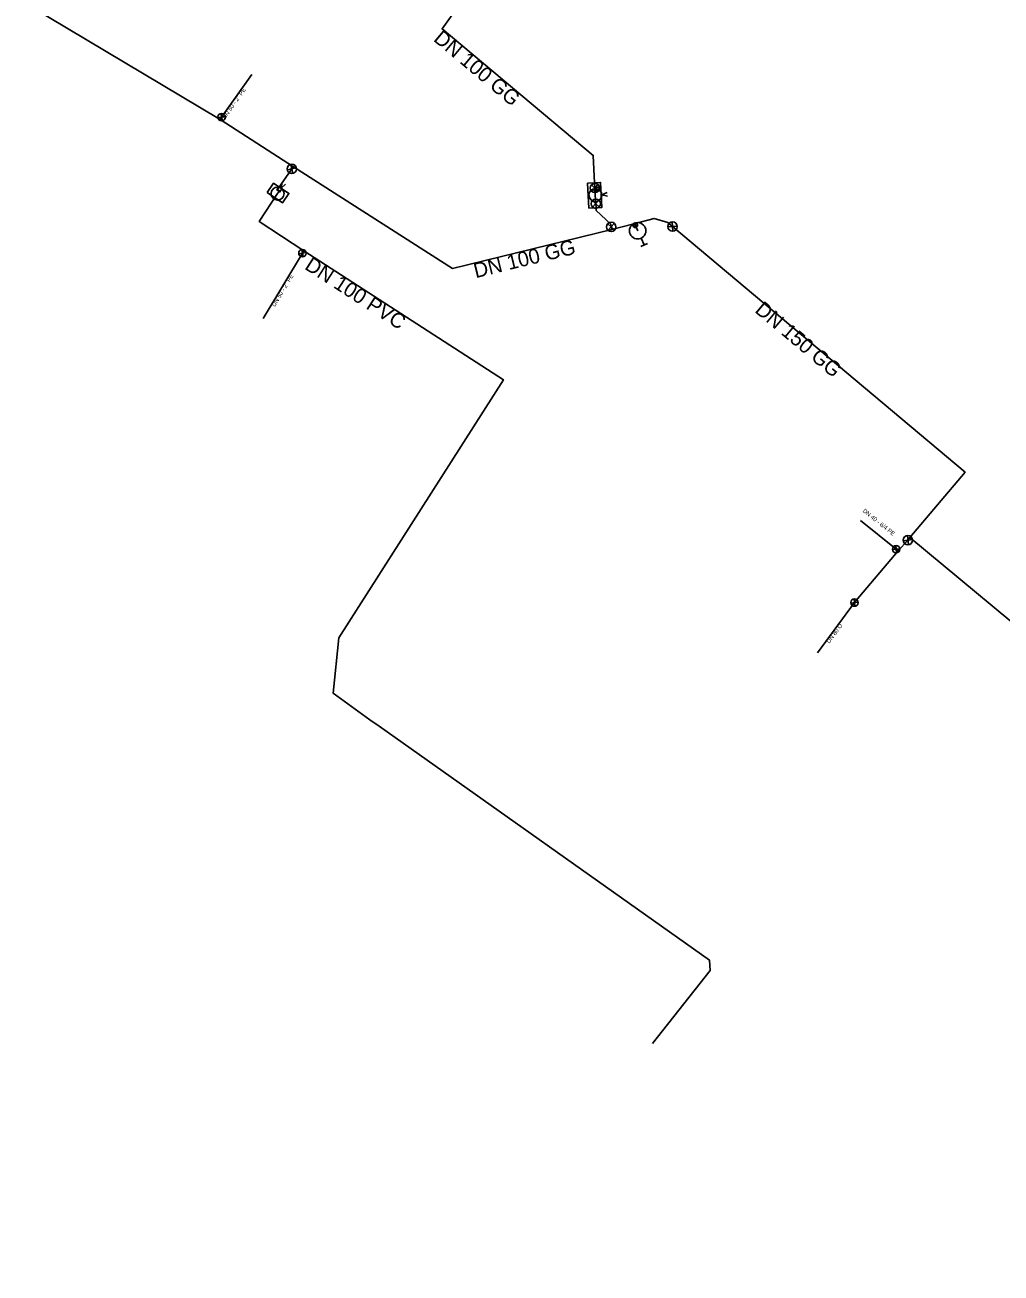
# Model space of a CAD drawing. Extents: x -443519 to -443021, y -1121477 to -1120870.
# Drawn here: x -443286.9 to -443181.7, y -1121441.8 to -1121307.3 of the extents above; entities that cross this region are included whole.
import ezdxf

# ---------------------------------------------------------------- set-up
doc = ezdxf.new("R2010")
doc.units = 0
for name, color, linetype in [('_hydrantova_odbocka_', 7, 'Continuous'), ('_pripojka_priblizne_', 7, 'Continuous'), ('_sachta_voda_', 7, 'Continuous'), ('_voda_smvak_prevzato_z_dokumentace_', 7, 'Continuous'), ('_voda_smvak_priblizne_', 7, 'Continuous'), ('Default', 7, 'Continuous'), ('MoLevel 2', 7, 'Continuous'), ('MoLevel 27', 7, 'Continuous'), ('MoLevel 28', 7, 'Continuous'), ('MoLevel 30', 7, 'Continuous'), ('MoLevel 32', 7, 'Continuous'), ('MoLevel 42', 7, 'Continuous'), ('MoLevel 46', 7, 'Continuous'), ('MoLevel 53', 7, 'Continuous')]:
    doc.layers.add(name, color=color, linetype=linetype)

# ---------------------------------------------------------------- blocks, each defined once
blk = doc.blocks.new('_uzaver_')
at = {"layer": 'Default'}
for p, q in [((-0.000035, -0.000035), (0.000035, 0.000035)), ((0.000035, -0.000035), (-0.000035, 0.000035))]:
    blk.add_line(p, q, dxfattribs=at)
for radius in [0.00005, 0.0000025]:
    blk.add_circle((0, 0), radius, dxfattribs=at)
blk = doc.blocks.new('_uzaver_pripojka_')
at = {"layer": 'Default'}
for p, q in [((-0.000035, -0.000035), (0.000035, 0.000035)), ((0.000035, -0.000035), (-0.000035, 0.000035))]:
    blk.add_line(p, q, dxfattribs=at)
for radius in [0.00005, 0.0000025]:
    blk.add_circle((0, 0), radius, dxfattribs=at)
blk = doc.blocks.new('_hydrant_voda_')
at = {"layer": 'Default'}
for p, q in [((-0.0000225, 0.000095), (0.0000225, 0.000095)), ((0, 0.000095), (0, 0.00005))]:
    blk.add_line(p, q, dxfattribs=at)
blk.add_circle((0, 0), 0.00005, dxfattribs=at)
blk = doc.blocks.new('_sachta_voda_')
at = {"layer": 'Default'}
blk.add_lwpolyline([(-0.00001, 0.000065), (0, 0.000035), (0.00001, 0.000065)], dxfattribs=at)
blk.add_circle((0, 0), 0.000035, dxfattribs=at)
blk = doc.blocks.new('_poklop_voda_')
at = {"layer": 'Default'}
blk.add_lwpolyline([(-0.00002, 0.00002), (0.00002, 0.00002), (0.00002, -0.00002), (-0.00002, -0.00002), (-0.00002, 0.00002)], dxfattribs=at)

msp = doc.modelspace()

# ---------------------------------------------------------------- linework, layer by layer
at = {"layer": '_hydrantova_odbocka_'}
msp.add_lwpolyline([(-443220.87, -1121329.47), (-443221.13, -1121328.87), (-443221.29, -1121328.71)], dxfattribs=at)
at = {"layer": '_pripojka_priblizne_'}
for points in [[(-443265.87, -1121317.47), (-443265.71, -1121317.22), (-443262.46, -1121312.62)], [(-443256.84, -1121331.63), (-443257, -1121331.88), (-443261.24, -1121338.93)], [(-443192.78, -1121363.96), (-443193.02, -1121363.78), (-443196.87, -1121360.69)], [(-443197.36, -1121369.35), (-443197.51, -1121369.53), (-443201.5, -1121374.95)]]:
    msp.add_lwpolyline(points, dxfattribs=at)
at = {"layer": '_sachta_voda_'}
for points in [[(-443260.79, -1121325.34), (-443260.13, -1121324.34), (-443258.46, -1121325.45), (-443259.13, -1121326.45)], [(-443226.26, -1121324.33), (-443224.86, -1121324.26), (-443224.73, -1121326.95), (-443226.12, -1121327.02)]]:
    msp.add_lwpolyline(points, close=True, dxfattribs=at)
at = {"layer": '_voda_smvak_prevzato_z_dokumentace_'}
for p, q in [((-443258.14, -1121322.8), (-443257.96, -1121322.56)), ((-443225.48, -1121324.86), (-443225.51, -1121324.29)), ((-443225.44, -1121325.62), (-443225.48, -1121324.86)), ((-443225.39, -1121326.55), (-443225.44, -1121325.62)), ((-443225.36, -1121327), (-443225.39, -1121326.55)), ((-443223.65, -1121329.34), (-443223.72, -1121329.05)), ((-443223.65, -1121329.34), (-443221.29, -1121328.71)), ((-443191.53, -1121362.52), (-443191.75, -1121362.8))]:
    msp.add_line(p, q, dxfattribs=at)
for points in [[(-443225.51, -1121324.29), (-443225.66, -1121321.35), (-443241.94, -1121307.71), (-443231.14, -1121292.5)], [(-443286.9, -1121304.94), (-443284.46, -1121306.39), (-443265.87, -1121317.47), (-443257.96, -1121322.56)], [(-443257.96, -1121322.56), (-443240.83, -1121333.54), (-443223.65, -1121329.34)], [(-443221.29, -1121328.71), (-443219.09, -1121328.13), (-443217.62, -1121328.57), (-443217.11, -1121329.01)], [(-443217.11, -1121329.01), (-443185.58, -1121355.49), (-443191.53, -1121362.52)], [(-443191.75, -1121362.8), (-443192.78, -1121363.96), (-443197.36, -1121369.35)], [(-443191.53, -1121362.52), (-443168.1, -1121381.98), (-443151.73, -1121395.63), (-443135.91, -1121409.91), (-443094.07, -1121441.77)]]:
    msp.add_lwpolyline(points, dxfattribs=at)
at = {"layer": '_voda_smvak_priblizne_'}
for points in [[(-443259.67, -1121325.46), (-443259.47, -1121325.16), (-443259.68, -1121325.02), (-443258.14, -1121322.8)], [(-443219.27, -1121417.02), (-443213.06, -1121409.16), (-443213.13, -1121408.05), (-443248.73, -1121382.84), (-443249.73, -1121382.15), (-443253.68, -1121379.29), (-443253.08, -1121373.32), (-443235.33, -1121345.51), (-443256.84, -1121331.63), (-443261.66, -1121328.46), (-443259.67, -1121325.46)], [(-443223.72, -1121329.05), (-443223.78, -1121328.76), (-443225.34, -1121327.29), (-443225.36, -1121327)]]:
    msp.add_lwpolyline(points, dxfattribs=at)

# ---------------------------------------------------------------- block references
at = {"layer": 'MoLevel 27'}
for p, xscale, yscale, rotation in [((-443258.14, -1121322.8), 10000.000000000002, 10000, 56.3839305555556), ((-443225.48, -1121324.86), 10000.000000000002, 10000, 92.8773555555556), ((-443225.39, -1121326.55), 10000.000000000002, 10000, 92.8773555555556), ((-443223.72, -1121329.05), 10000, 9999.999999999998, -86.96504444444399), ((-443221.13, -1121328.87), 5000, 5000, -65.08720605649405), ((-443217.11, -1121329.01), 10000, 10000, -40.02100274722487), ((-443191.75, -1121362.8), 10000, 10000, -128.2645704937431)]:
    msp.add_blockref('_uzaver_', p, dxfattribs=dict(at, xscale=xscale, yscale=yscale, rotation=rotation))
at = {"layer": 'MoLevel 28', "xscale": 17636.68430335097, "yscale": 17636.68430335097, "rotation": -155.68131957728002}
msp.add_blockref('_hydrant_voda_', (-443220.87, -1121329.47), dxfattribs=at)
at = {"layer": 'MoLevel 30', "xscale": 20000, "yscale": 20000}
for p, rotation in [((-443259.67, -1121325.46), -31.282653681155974), ((-443225.43, -1121325.62), -86.96230833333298)]:
    msp.add_blockref('_sachta_voda_', p, dxfattribs=dict(at, rotation=rotation))
at = {"layer": 'MoLevel 42', "xscale": 10000}
for p, yscale, rotation in [((-443259.48, -1121325.01), 10000, -32.140995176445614), ((-443225.21, -1121324.99), 10000.000000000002, -86.30436850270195)]:
    msp.add_blockref('_poklop_voda_', p, dxfattribs=dict(at, yscale=yscale, rotation=rotation))
at = {"layer": 'MoLevel 53'}
for p, xscale, yscale, rotation in [((-443265.71, -1121317.22), 8000, 7999.999999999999, 57.5289840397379), ((-443257, -1121331.88), 7999.999999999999, 7999.999999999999, -124.9920201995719), ((-443193.02, -1121363.78), 7999.999999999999, 7999.999999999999, 139.580617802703), ((-443197.51, -1121369.53), 7999.999999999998, 8000, 51.73308055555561)]:
    msp.add_blockref('_uzaver_pripojka_', p, dxfattribs=dict(at, xscale=xscale, yscale=yscale, rotation=rotation))

# ---------------------------------------------------------------- texts
at = {"layer": 'MoLevel 2'}
msp.add_text('DN 100 PVC', height=1.605, rotation=327.157, dxfattribs=at).set_placement((-443256.86, -1121333.52))
at = {"layer": 'MoLevel 32'}
for s, rotation, p in [("DN 50 - 2'' PE", 54.7307, (-443265.33, -1121317.48)), ("DN 50 - 2'' PE", 58.9862, (-443259.96, -1121337.69)), ('DN 40 - 6/4 PE', 321.2138, (-443196.66, -1121359.72)), ('DN 80 O', 53.6029, (-443200.22, -1121373.97))]:
    msp.add_text(s, height=0.455, rotation=rotation, dxfattribs=at).set_placement(p)
at = {"layer": 'MoLevel 46'}
for s, rotation, p in [('DN 100 GG', 320.029, (-443242.97, -1121308.94)), ('DN 100 GG', 13.7321, (-443238.33, -1121334.58)), ('DN 150 GG', 319.9761, (-443208.34, -1121338.17))]:
    msp.add_text(s, height=1.605, rotation=rotation, dxfattribs=at).set_placement(p)

doc.saveas('drawing.dxf')
